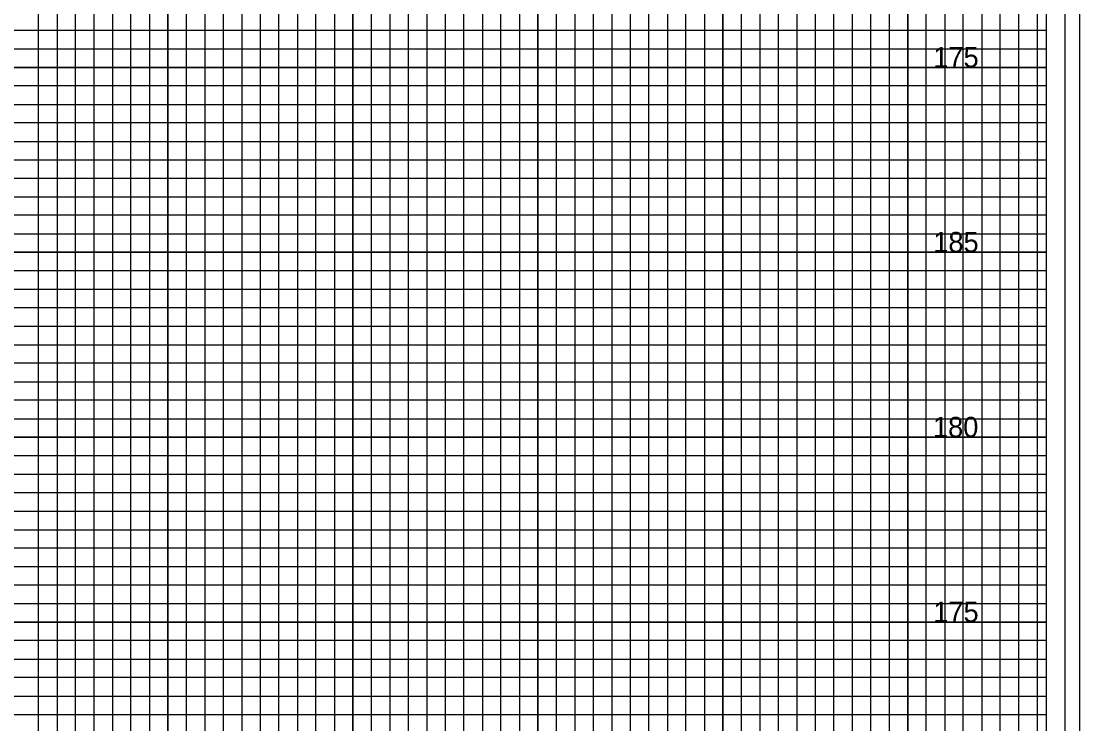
# Model space of a CAD drawing. Extents: x -4 to 103, y -2 to 209.
# Drawn here: x 74.78 to 103.4, y 32.25 to 51.25 of the extents above; entities that cross this region are included whole.
import ezdxf

# ---------------------------------------------------------------- set-up
doc = ezdxf.new("R2010")
doc.units = 0
for name, color, linetype in [('Old_Level_10', 7, 'Continuous'), ('Old_Level_4', 7, 'Continuous'), ('Old_Level_5', 7, 'Continuous'), ('Old_Level_6', 7, 'Continuous'), ('Old_Level_8', 7, 'Continuous'), ('Prop Dimension', 7, 'Continuous'), ('Prop XS Subgrade Earthwork', 7, 'Continuous')]:
    doc.layers.add(name, color=color, linetype=linetype)

msp = doc.modelspace()

# ---------------------------------------------------------------- linework, layer by layer
at = {"layer": 'Old_Level_10'}
for p, q in [((91.25, 0), (91.25, 63.425)), ((93.75, 0), (93.75, 63.425)), ((96.25, 0), (96.25, 63.425)), ((98.75, 0), (98.75, 63.425)), ((101.25, 0), (101.25, 63.425)), ((76.25, 0), (76.25, 62)), ((78.75, 0), (78.75, 62)), ((81.25, 0), (81.25, 62)), ((83.75, 0), (83.75, 62)), ((86.25, 0), (86.25, 62)), ((88.75, 0), (88.75, 62)), ((0, 50), (102.5, 50)), ((0, 47.5), (102.5, 47.5)), ((0, 45), (102.5, 45)), ((0, 42.5), (102.5, 42.5)), ((0, 40), (102.5, 40)), ((0, 37.5), (102.5, 37.5)), ((0, 35), (102.5, 35)), ((0, 32.5), (102.5, 32.5))]:
    msp.add_line(p, q, dxfattribs=at)
at = {"layer": 'Old_Level_4'}
msp.add_lwpolyline([(103, 66), (-2.8, 66), (-2.8, -1), (103, -1)], close=True, dxfattribs=at)
at = {"layer": 'Old_Level_5'}
msp.add_lwpolyline([(103.4, 67.4), (-3.5, 67.4), (-3.5, -2.425), (103.4, -2.425)], close=True, dxfattribs=at)
at = {"layer": 'Old_Level_6'}
msp.add_lwpolyline([(102.5, 65), (0, 65), (0, 0), (102.5, 0)], close=True, dxfattribs=at)
at = {"layer": 'Old_Level_8'}
for points in [[(91.25, 0), (91.25, 63.425), (93.75, 63.425), (93.75, 0)], [(96.25, 0), (96.25, 63.425), (98.75, 63.425), (98.75, 0)], [(101.25, 0), (101.25, 63.425)], [(76.25, 0), (76.25, 62), (78.75, 62), (78.75, 0)], [(81.25, 0), (81.25, 62), (83.75, 62), (83.75, 0)], [(86.25, 0), (86.25, 62), (88.75, 62), (88.75, 0)], [(0, 47.5), (102.5, 47.5), (102.5, 50), (0, 50)], [(0, 42.5), (102.5, 42.5), (102.5, 45), (0, 45)], [(0, 37.5), (102.5, 37.5), (102.5, 40), (0, 40)], [(0, 32.5), (102.5, 32.5), (102.5, 35), (0, 35)]]:
    msp.add_lwpolyline(points, dxfattribs=at)
at = {"layer": 'Prop Dimension'}
for points in [[(90.25, 0), (90.25, 63.425), (90.75, 63.425), (90.75, 0)], [(91.75, 0), (91.75, 63.425), (92.25, 63.425), (92.25, 0)], [(92.75, 0), (92.75, 63.425), (93.25, 63.425), (93.25, 0)], [(94.25, 0), (94.25, 63.425), (94.75, 63.425), (94.75, 0)], [(95.25, 0), (95.25, 63.425), (95.75, 63.425), (95.75, 0)], [(96.75, 0), (96.75, 63.425), (97.25, 63.425), (97.25, 0)], [(97.75, 0), (97.75, 63.425), (98.25, 63.425), (98.25, 0)], [(99.25, 0), (99.25, 63.425), (99.75, 63.425), (99.75, 0)], [(100.25, 0), (100.25, 63.425)], [(100.25, 63.425), (100.75, 63.425), (100.75, 0), (101.75, 0), (101.75, 63.425), (102.25, 63.425), (102.25, 0)], [(75.25, 0), (75.25, 62), (75.75, 62), (75.75, 0)], [(76.75, 0), (76.75, 62), (77.25, 62), (77.25, 0)], [(77.75, 0), (77.75, 62), (78.25, 62), (78.25, 0)], [(79.25, 0), (79.25, 62), (79.75, 62), (79.75, 0)], [(80.25, 0), (80.25, 62), (80.75, 62), (80.75, 0)], [(81.75, 0), (81.75, 62), (82.25, 62), (82.25, 0)], [(82.75, 0), (82.75, 62), (83.25, 62), (83.25, 0)], [(84.25, 0), (84.25, 62), (84.75, 62), (84.75, 0)], [(85.25, 0), (85.25, 62), (85.75, 62), (85.75, 0)], [(86.75, 0), (86.75, 62), (87.25, 62), (87.25, 0)], [(87.75, 0), (87.75, 62), (88.25, 62), (88.25, 0)], [(89.25, 0), (89.25, 62), (89.75, 62), (89.75, 0)], [(0, 50.5), (102.5, 50.5), (102.5, 51), (0, 51)], [(0, 49), (102.5, 49), (102.5, 49.5), (0, 49.5)], [(0, 48), (102.5, 48), (102.5, 48.5), (0, 48.5)], [(0, 46.5), (102.5, 46.5), (102.5, 47), (0, 47)], [(0, 45.5), (102.5, 45.5), (102.5, 46), (0, 46)], [(0, 44), (102.5, 44), (102.5, 44.5), (0, 44.5)], [(0, 43), (102.5, 43), (102.5, 43.5), (0, 43.5)], [(0, 41.5), (102.5, 41.5), (102.5, 42), (0, 42)], [(0, 40.5), (102.5, 40.5), (102.5, 41), (0, 41)], [(0, 39), (102.5, 39), (102.5, 39.5), (0, 39.5)], [(0, 38), (102.5, 38), (102.5, 38.5), (0, 38.5)], [(0, 36.5), (102.5, 36.5), (102.5, 37), (0, 37)], [(0, 35.5), (102.5, 35.5), (102.5, 36), (0, 36)], [(0, 34), (102.5, 34), (102.5, 34.5), (0, 34.5)], [(0, 33), (102.5, 33), (102.5, 33.5), (0, 33.5)]]:
    msp.add_lwpolyline(points, dxfattribs=at)

# ---------------------------------------------------------------- texts
at = {"layer": 'Prop XS Subgrade Earthwork'}
for s, p in [('175', (99.4383, 50)), ('185', (99.4383, 45)), ('180', (99.4296, 40)), ('175', (99.4383, 35))]:
    msp.add_text(s, height=0.55, dxfattribs=at).set_placement(p)

doc.saveas('drawing.dxf')
